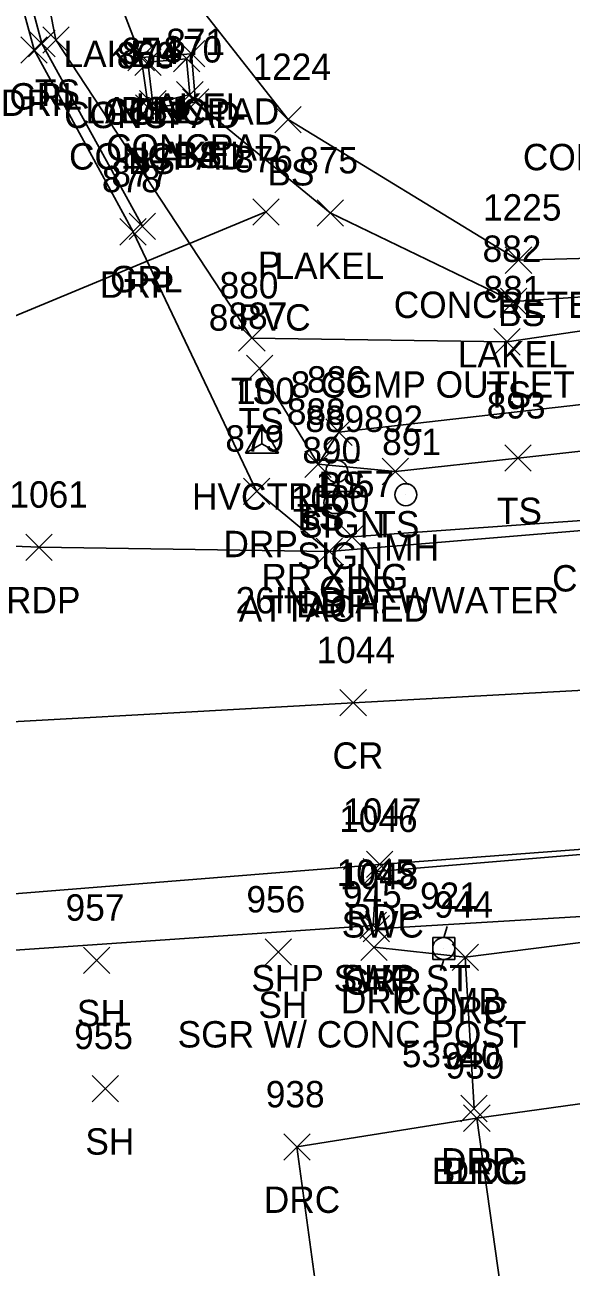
# Model space of a CAD drawing. Extents: x 1716490 to 1717645, y 888034 to 890004.
# Drawn here: x 1716813.5 to 1716855, y 888185.6 to 888279.7 of the extents above; entities that cross this region are included whole.
import ezdxf

# ---------------------------------------------------------------- set-up
doc = ezdxf.new("R2010")
doc.units = 0
for name, color, linetype in [('C_A', 7, 'Continuous'), ('C_I', 7, 'Continuous'), ('CPSM', 7, 'Continuous'), ('D_A', 7, 'Continuous'), ('D_C', 7, 'Continuous'), ('D_I', 7, 'Continuous'), ('D_TIC', 7, 'Continuous'), ('DCP', 7, 'Continuous'), ('L_A', 7, 'Continuous'), ('L_I', 7, 'Continuous'), ('L_TIC', 7, 'Continuous'), ('LAWE', 7, 'Continuous'), ('LBC', 7, 'Continuous'), ('LELB', 7, 'Continuous'), ('LS', 7, 'Continuous'), ('P_A', 7, 'Continuous'), ('P_I', 7, 'Continuous'), ('P_TIC', 7, 'Continuous'), ('PET', 7, 'Continuous'), ('PRC', 7, 'Continuous'), ('PSP', 7, 'Continuous'), ('R_A', 7, 'Continuous'), ('R_C', 7, 'Continuous'), ('R_I', 7, 'Continuous'), ('R_TIC', 7, 'Continuous'), ('RDP', 7, 'Continuous'), ('RGR', 7, 'Continuous'), ('RSW', 7, 'Continuous'), ('S_A', 7, 'Continuous'), ('S_C', 7, 'Continuous'), ('S_I', 7, 'Continuous'), ('SSGN', 7, 'Continuous'), ('U_A', 7, 'Continuous'), ('U_C', 7, 'Continuous'), ('U_I', 7, 'Continuous'), ('UP', 7, 'Continuous'), ('UUMH', 7, 'Continuous')]:
    doc.layers.add(name, color=color, linetype=linetype)

msp = doc.modelspace()

# ---------------------------------------------------------------- linework, layer by layer
at = {"layer": 'CPSM'}
for p, q in [((1716830.281, 888247.276), (1716831.531, 888249.441)), ((1716832.781, 888247.276), (1716831.531, 888249.441)), ((1716831.531, 888247.997), (1716831.531, 888249.441)), ((1716830.281, 888247.276), (1716831.531, 888247.997)), ((1716831.531, 888247.997), (1716831.531, 888247.997)), ((1716831.531, 888247.997), (1716832.781, 888247.276)), ((1716830.281, 888247.276), (1716832.781, 888247.276))]:
    msp.add_line(p, q, dxfattribs=at)
at = {"layer": 'D_TIC'}
for points in [[(1716830.837, 888264.562), (1716832.837, 888266.562)], [(1716832.837, 888264.562), (1716830.837, 888266.562)]]:
    msp.add_lwpolyline(points, dxfattribs=at)
at = {"layer": 'DCP'}
msp.add_lwpolyline([(1716831.837, 888265.562), (1716770.869, 888240.276)], dxfattribs=at)
at = {"layer": 'L_TIC'}
for points in [[(1716814.908, 888277.599), (1716816.908, 888279.599)], [(1716816.908, 888277.599), (1716814.908, 888279.599)], [(1716821.371, 888276.267), (1716823.371, 888278.267)], [(1716823.371, 888276.267), (1716821.371, 888278.267)], [(1716821.371, 888276.267), (1716823.371, 888278.267)], [(1716823.371, 888276.267), (1716821.371, 888278.267)], [(1716821.882, 888275.912), (1716823.882, 888277.912)], [(1716823.882, 888275.912), (1716821.882, 888277.912)], [(1716824.821, 888276.17), (1716826.821, 888278.17)], [(1716826.821, 888276.17), (1716824.821, 888278.17)], [(1716825.189, 888276.556), (1716827.189, 888278.556)], [(1716827.189, 888276.556), (1716825.189, 888278.556)], [(1716825.062, 888273.45), (1716827.062, 888275.45)], [(1716827.062, 888273.45), (1716825.062, 888275.45)], [(1716825.504, 888272.884), (1716827.504, 888274.884)], [(1716827.504, 888272.884), (1716825.504, 888274.884)], [(1716825.504, 888272.884), (1716827.504, 888274.884)], [(1716827.504, 888272.884), (1716825.504, 888274.884)], [(1716821.932, 888272.438), (1716823.932, 888274.438)], [(1716823.932, 888272.438), (1716821.932, 888274.438)], [(1716822.255, 888272.772), (1716824.255, 888274.772)], [(1716824.255, 888272.772), (1716822.255, 888274.772)], [(1716832.507, 888271.565), (1716834.507, 888273.565)], [(1716834.507, 888271.565), (1716832.507, 888273.565)], [(1716835.716, 888264.482), (1716837.716, 888266.482)], [(1716837.716, 888264.482), (1716835.716, 888266.482)], [(1716849.988, 888260.906), (1716851.988, 888262.906)], [(1716851.988, 888260.906), (1716849.988, 888262.906)], [(1716849.622, 888257.774), (1716851.622, 888259.774)], [(1716851.622, 888257.774), (1716849.622, 888259.774)], [(1716829.764, 888255.002), (1716831.764, 888257.002)], [(1716831.764, 888255.002), (1716829.764, 888257.002)], [(1716849.124, 888254.716), (1716851.124, 888256.716)], [(1716851.124, 888254.716), (1716849.124, 888256.716)], [(1716830.352, 888252.697), (1716832.352, 888254.697)], [(1716832.352, 888252.697), (1716830.352, 888254.697)], [(1716836.365, 888247.868), (1716838.365, 888249.868)], [(1716838.365, 888247.868), (1716836.365, 888249.868)], [(1716849.938, 888245.905), (1716851.938, 888247.905)], [(1716851.938, 888245.905), (1716849.938, 888247.905)], [(1716834.782, 888245.432), (1716836.782, 888247.432)], [(1716836.782, 888245.432), (1716834.782, 888247.432)], [(1716834.782, 888245.432), (1716836.782, 888247.432)], [(1716836.782, 888245.432), (1716834.782, 888247.432)], [(1716840.647, 888244.886), (1716842.647, 888246.886)], [(1716842.647, 888244.886), (1716840.647, 888246.886)], [(1716818.002, 888207.843), (1716820.002, 888209.843)], [(1716820.002, 888207.843), (1716818.002, 888209.843)], [(1716831.77, 888208.468), (1716833.77, 888210.468)], [(1716833.77, 888208.468), (1716831.77, 888210.468)], [(1716818.65, 888198.11), (1716820.65, 888200.11)], [(1716820.65, 888198.11), (1716818.65, 888200.11)], [(1716846.826, 888195.875), (1716848.826, 888197.875)], [(1716848.826, 888195.875), (1716846.826, 888197.875)]]:
    msp.add_lwpolyline(points, dxfattribs=at)
at = {"layer": 'LAWE'}
msp.add_lwpolyline([(1716792.923, 888333.593), (1716808.09, 888324.58), (1716820.08, 888290.735), (1716820.719, 888281.539), (1716822.371, 888277.267), (1716826.189, 888277.556), (1716826.504, 888273.884), (1716836.716, 888265.482), (1716850.622, 888258.774), (1716877.174, 888260.555), (1716881.322, 888255.897), (1716887.736, 888253.856), (1716892.995, 888253.305), (1716893.169, 888249.274), (1716879.794, 888244.823)], dxfattribs=at)
at = {"layer": 'LBC'}
msp.add_lwpolyline([(1716884.889, 888132.553), (1716884.371, 888132.666), (1716857.375, 888128.726), (1716852.404, 888164.292), (1716847.826, 888196.875), (1716876.377, 888200.838), (1716883.534, 888201.862), (1716883.701, 888201.987), (1716884.835, 888201.978)], dxfattribs=at)
at = {"layer": 'LELB'}
for points in [[(1716798.784, 888338.684), (1716807.198, 888328.202), (1716816.689, 888310.638), (1716822.622, 888293.629), (1716826.404, 888294.991), (1716827.92, 888291.14), (1716823.715, 888289.67), (1716822.512, 888293.041), (1716821.152, 888288.315), (1716833.507, 888272.565), (1716850.988, 888261.906), (1716864.723, 888262.295), (1716881.119, 888261.054)], [(1716791.288, 888331.615), (1716796.122, 888325.707), (1716805.751, 888321.457), (1716813.357, 888291.514), (1716815.908, 888278.599), (1716830.764, 888256.002), (1716850.124, 888255.716), (1716867.758, 888258.309)], [(1716822.371, 888277.267), (1716822.932, 888273.438), (1716826.504, 888273.884)], [(1716831.352, 888253.697), (1716835.782, 888246.432), (1716841.647, 888245.886), (1716850.938, 888246.905), (1716869.789, 888249.001), (1716870.22, 888257.561), (1716875.534, 888257.948), (1716880.311, 888254.139), (1716887.482, 888251.965), (1716891.986, 888252.334), (1716891.594, 888250.562), (1716886.869, 888248.35), (1716879.09, 888248.225)], [(1716867.758, 888258.309), (1716868.17, 888252.377), (1716837.365, 888248.868), (1716835.782, 888246.432)]]:
    msp.add_lwpolyline(points, dxfattribs=at)
at = {"layer": 'LS'}
for points in [[(1716826.062, 888274.45), (1716825.821, 888277.17), (1716822.882, 888276.912), (1716823.255, 888273.772)], [(1716823.255, 888273.772), (1716826.062, 888274.45)]]:
    msp.add_lwpolyline(points, dxfattribs=at)
at = {"layer": 'P_TIC'}
for points in [[(1716813.633, 888239.145), (1716815.633, 888241.145)], [(1716815.633, 888239.145), (1716813.633, 888241.145)], [(1716835.634, 888238.831), (1716837.634, 888240.831)], [(1716837.634, 888238.831), (1716835.634, 888240.831)], [(1716837.45, 888227.358), (1716839.45, 888229.358)], [(1716839.45, 888227.358), (1716837.45, 888229.358)], [(1716839.455, 888215.113), (1716841.455, 888217.113)], [(1716841.455, 888215.113), (1716839.455, 888217.113)], [(1716838.964, 888210.481), (1716840.964, 888212.481)], [(1716840.964, 888210.481), (1716838.964, 888212.481)]]:
    msp.add_lwpolyline(points, dxfattribs=at)
at = {"layer": 'PET'}
msp.add_lwpolyline([(1716669.133, 888208.315), (1716709.505, 888208.714), (1716740.373, 888211.068), (1716775.556, 888211.777), (1716802.021, 888213.013), (1716840.455, 888216.113), (1716878.657, 888218.974), (1716877.597, 888230.504), (1716876.883, 888242.851), (1716857.915, 888241.594), (1716836.634, 888239.831), (1716814.633, 888240.145), (1716785.061, 888241.323), (1716771.928, 888239.872), (1716746.815, 888241.658), (1716719.438, 888242.78), (1716699.752, 888242.907), (1716680.829, 888242.531), (1716671.322, 888244.592)], dxfattribs=at)
at = {"layer": 'PRC'}
msp.add_lwpolyline([(1716669.076, 888220.596), (1716706.499, 888221.389), (1716739.728, 888221.602), (1716772.982, 888225.054), (1716801.229, 888226.279), (1716838.45, 888228.358), (1716877.597, 888230.504)], dxfattribs=at)
at = {"layer": 'PSP'}
msp.add_lwpolyline([(1716669.372, 888204.532), (1716709.372, 888205.407), (1716740.477, 888206.521), (1716776.451, 888207.971), (1716801.777, 888208.857), (1716839.964, 888211.481)], dxfattribs=at)
at = {"layer": 'R_TIC'}
for points in [[(1716813.245, 888276.838), (1716815.245, 888278.838)], [(1716815.245, 888276.838), (1716813.245, 888278.838)], [(1716813.838, 888277.323), (1716815.838, 888279.323)], [(1716815.838, 888277.323), (1716813.838, 888279.323)], [(1716821.467, 888263.473), (1716823.467, 888265.473)], [(1716823.467, 888263.473), (1716821.467, 888265.473)], [(1716820.755, 888263.054), (1716822.755, 888265.054)], [(1716822.755, 888263.054), (1716820.755, 888265.054)], [(1716830.123, 888243.394), (1716832.123, 888245.394)], [(1716832.123, 888243.394), (1716830.123, 888245.394)], [(1716837.37, 888239.943), (1716839.37, 888241.943)], [(1716839.37, 888239.943), (1716837.37, 888241.943)], [(1716835.634, 888238.831), (1716837.634, 888240.831)], [(1716837.634, 888238.831), (1716835.634, 888240.831)], [(1716839.214, 888214.564), (1716841.214, 888216.564)], [(1716841.214, 888214.564), (1716839.214, 888216.564)], [(1716838.964, 888210.481), (1716840.964, 888212.481)], [(1716840.964, 888210.481), (1716838.964, 888212.481)], [(1716839.215, 888210.23), (1716841.215, 888212.23)], [(1716841.215, 888210.23), (1716839.215, 888212.23)], [(1716839.032, 888208.825), (1716841.032, 888210.825)], [(1716841.032, 888208.825), (1716839.032, 888210.825)], [(1716845.948, 888208.068), (1716847.948, 888210.068)], [(1716847.948, 888208.068), (1716845.948, 888210.068)], [(1716845.948, 888208.068), (1716847.948, 888210.068)], [(1716847.948, 888208.068), (1716845.948, 888210.068)], [(1716846.619, 888196.606), (1716848.619, 888198.606)], [(1716848.619, 888196.606), (1716846.619, 888198.606)], [(1716846.826, 888195.875), (1716848.826, 888197.875)], [(1716848.826, 888195.875), (1716846.826, 888197.875)], [(1716833.184, 888193.695), (1716835.184, 888195.695)], [(1716835.184, 888193.695), (1716833.184, 888195.695)]]:
    msp.add_lwpolyline(points, dxfattribs=at)
at = {"layer": 'RDP'}
for points in [[(1716788.401, 888319.776), (1716804.113, 888319.602), (1716810.581, 888291.273), (1716814.245, 888277.838), (1716821.755, 888264.054), (1716831.123, 888244.394), (1716836.634, 888239.831)], [(1716876.377, 888200.838), (1716875.716, 888209.526), (1716867.474, 888211.687), (1716846.948, 888209.068)], [(1716847.619, 888197.606), (1716846.948, 888209.068), (1716840.032, 888209.825)], [(1716857.375, 888128.726), (1716843.611, 888126.909), (1716838.26, 888164.679), (1716834.184, 888194.695), (1716847.826, 888196.875)]]:
    msp.add_lwpolyline(points, dxfattribs=at)
at = {"layer": 'RGR'}
for points in [[(1716789.776, 888320.755), (1716804.987, 888320.51), (1716811.337, 888291.322), (1716814.838, 888278.323), (1716822.467, 888264.473)], [(1716877.112, 888243.702), (1716838.37, 888240.943)], [(1716840.215, 888211.23), (1716878.419, 888213.528)]]:
    msp.add_lwpolyline(points, dxfattribs=at)
at = {"layer": 'RSW'}
msp.add_lwpolyline([(1716839.964, 888211.481), (1716840.214, 888215.564), (1716878.468, 888218.75), (1716878.816, 888213.646)], dxfattribs=at)
at = {"layer": 'SSGN'}
for p, q in [((1716835.56, 888246.736), (1716838.893, 888246.736)), ((1716837.206, 888245.903), (1716837.206, 888245.903)), ((1716835.414, 888244.361), (1716838.747, 888244.361)), ((1716837.061, 888243.527), (1716837.061, 888243.527))]:
    msp.add_line(p, q, dxfattribs=at)
for centre in [(1716837.206, 888245.903), (1716837.061, 888243.527)]:
    msp.add_circle(centre, 0.833, dxfattribs=at)
at = {"layer": 'UP'}
for p, q in [((1716845.569, 888211.403), (1716845.319, 888210.57)), ((1716844.485, 888208.903), (1716844.485, 888210.57)), ((1716844.485, 888210.57), (1716846.152, 888210.57)), ((1716846.152, 888210.57), (1716846.152, 888208.903)), ((1716846.152, 888208.903), (1716844.485, 888208.903)), ((1716845.069, 888208.07), (1716845.319, 888208.903)), ((1716845.319, 888209.737), (1716845.319, 888209.737))]:
    msp.add_line(p, q, dxfattribs=at)
msp.add_circle((1716845.319, 888209.737), 0.833, dxfattribs=at)
at = {"layer": 'UUMH'}
for p, q in [((1716842.442, 888244.13), (1716842.442, 888244.13)), ((1716843.275, 888244.13), (1716843.275, 888244.13))]:
    msp.add_line(p, q, dxfattribs=at)
msp.add_circle((1716842.442, 888244.13), 0.833, dxfattribs=at)

# ---------------------------------------------------------------- texts
at = {"layer": 'C_A'}
msp.add_text('HVCTRL', height=2, dxfattribs=at).set_placement((1716826.224, 888242.997))
at = {"layer": 'C_I'}
msp.add_text('100', height=2, dxfattribs=at).set_placement((1716829.571, 888250.997))
at = {"layer": 'D_A'}
msp.add_text('P', height=2, dxfattribs=at).set_placement((1716831.215, 888260.562))
at = {"layer": 'D_C'}
for s, p in [('8 PVC', (1716827.498, 888256.562)), ('8 CGMP OUTLET ORIGIN UNKNOWN', (1716833.708, 888251.48))]:
    msp.add_text(s, height=2, dxfattribs=at).set_placement(p)
at = {"layer": 'D_I'}
msp.add_text('876', height=2, dxfattribs=at).set_placement((1716829.42, 888268.562))
at = {"layer": 'L_A'}
for s, p in [('LAKEL', (1716816.483, 888276.539)), ('TS', (1716814.318, 888273.599)), ('CONCPAD', (1716816.528, 888271.912)), ('LAKEL', (1716818.135, 888272.267)), ('CONCPAD', (1716819.467, 888272.17)), ('BS', (1716820.812, 888272.267)), ('LAKEL', (1716821.953, 888272.556)), ('CONCPAD', (1716819.708, 888269.45)), ('CONCPAD', (1716816.901, 888268.772)), ('BS', (1716821.373, 888268.438)), ('LAKEL', (1716822.267, 888268.884)), ('BS', (1716824.944, 888268.884)), ('BS', (1716831.948, 888267.565)), ('LAKEL', (1716832.479, 888260.482)), ('BS', (1716849.429, 888256.906)), ('LAKEL', (1716846.386, 888253.774)), ('TS', (1716829.173, 888251.002)), ('TS', (1716848.533, 888250.716)), ('TS', (1716829.761, 888248.697)), ('BS', (1716835.805, 888243.868)), ('TS', (1716849.347, 888241.905)), ('TS', (1716834.192, 888241.432)), ('BS', (1716834.223, 888241.432)), ('TS', (1716840.056, 888240.886)), ('SH', (1716831.258, 888204.468)), ('SH', (1716817.49, 888203.843)), ('SH', (1716818.138, 888194.11)), ('BLDG', (1716844.417, 888191.875))]:
    msp.add_text(s, height=2, dxfattribs=at).set_placement(p)
at = {"layer": 'L_I'}
for s, p in [('874', (1716820.893, 888276.772)), ('870', (1716824.055, 888276.884)), ('870', (1716824.055, 888276.884)), ('871', (1716824.267, 888277.45)), ('869', (1716820.514, 888276.438)), ('1224', (1716830.814, 888275.565)), ('875', (1716834.353, 888268.482)), ('1225', (1716848.295, 888264.906)), ('882', (1716848.26, 888261.774)), ('880', (1716828.315, 888259.002)), ('881', (1716848.329, 888258.716)), ('887', (1716828.99, 888256.697)), ('886', (1716834.947, 888251.868)), ('888', (1716833.42, 888249.432)), ('888', (1716833.42, 888249.432)), ('893', (1716848.576, 888249.905)), ('892', (1716839.285, 888248.886)), ('957', (1716816.64, 888211.843)), ('956', (1716830.352, 888212.468)), ('955', (1716817.288, 888202.11)), ('939', (1716845.456, 888199.875))]:
    msp.add_text(s, height=2, dxfattribs=at).set_placement(p)
at = {"layer": 'P_A'}
for s, p in [('RDP', (1716812.121, 888235.145)), ('RDP', (1716834.122, 888234.831)), ('CR', (1716836.883, 888223.358)), ('RDP', (1716837.943, 888211.113)), ('SHP', (1716837.499, 888206.481))]:
    msp.add_text(s, height=2, dxfattribs=at).set_placement(p)
at = {"layer": 'P_I'}
for s, p in [('1061', (1716812.381, 888243.145)), ('1060', (1716833.728, 888242.831)), ('1044', (1716835.678, 888231.358)), ('1047', (1716837.683, 888219.113)), ('1045', (1716837.192, 888214.481))]:
    msp.add_text(s, height=2, dxfattribs=at).set_placement(p)
at = {"layer": 'R_A'}
for s, p in [('DRP', (1716811.733, 888272.838)), ('GRL', (1716812.382, 888273.323)), ('DRP', (1716819.243, 888259.054)), ('GRL', (1716820.011, 888259.473)), ('DRP', (1716828.611, 888239.394)), ('CURBC', (1716853.534, 888236.793)), ('GRR', (1716835.859, 888235.943)), ('DRP', (1716834.122, 888234.831)), ('SWC', (1716837.576, 888210.564)), ('SHP SWC ST', (1716830.727, 888206.481)), ('GRR', (1716837.703, 888206.23)), ('DRP', (1716837.52, 888204.825)), ('DRC', (1716844.436, 888204.068)), ('DRP', (1716844.436, 888204.068)), ('DRP', (1716845.107, 888192.606)), ('DRC', (1716845.314, 888191.875)), ('DRC', (1716831.672, 888189.695))]:
    msp.add_text(s, height=2, dxfattribs=at).set_placement(p)
at = {"layer": 'R_C'}
for s, p in [('CONCRETE 2.5 X 2', (1716851.32, 888268.72)), ('CONCRETE TIE TO LAST WITH RXR', (1716841.527, 888257.523)), ('SGR W/ CONC POST', (1716825.136, 888202.23))]:
    msp.add_text(s, height=2, dxfattribs=at).set_placement(p)
at = {"layer": 'R_I'}
for s, p in [('877', (1716820.105, 888267.473)), ('878', (1716819.393, 888267.054)), ('879', (1716828.753, 888247.394)), ('1057', (1716835.599, 888243.943)), ('1060', (1716833.728, 888242.831)), ('1046', (1716837.387, 888218.564)), ('1045', (1716837.192, 888214.481)), ('1048', (1716837.443, 888214.23)), ('945', (1716837.67, 888212.825)), ('944', (1716844.586, 888212.068)), ('944', (1716844.586, 888212.068)), ('940', (1716845.17, 888200.606)), ('939', (1716845.456, 888199.875)), ('938', (1716831.822, 888197.695))]:
    msp.add_text(s, height=2, dxfattribs=at).set_placement(p)
at = {"layer": 'S_A'}
for p in [(1716834.344, 888240.883), (1716834.198, 888238.507)]:
    msp.add_text('SIGN', height=2, dxfattribs=at).set_placement(p)
at = {"layer": 'S_C'}
for s, p in [('RR XING', (1716831.494, 888236.883)), ('ATTACHED', (1716829.773, 888234.507))]:
    msp.add_text(s, height=2, dxfattribs=at).set_placement(p)
at = {"layer": 'S_I'}
for s, p in [('889', (1716834.817, 888248.883)), ('890', (1716834.592, 888246.507))]:
    msp.add_text(s, height=2, dxfattribs=at).set_placement(p)
at = {"layer": 'U_A'}
for s, p in [('MH', (1716840.804, 888239.13)), ('COMB', (1716841.704, 888204.737))]:
    msp.add_text(s, height=2, dxfattribs=at).set_placement(p)
at = {"layer": 'U_C'}
for s, p in [('26IN DIA. WWATER', (1716829.537, 888235.13)), ('53-2', (1716842.137, 888200.737))]:
    msp.add_text(s, height=2, dxfattribs=at).set_placement(p)
at = {"layer": 'U_I'}
for s, p in [('891', (1716840.647, 888247.13)), ('921', (1716843.523, 888212.737))]:
    msp.add_text(s, height=2, dxfattribs=at).set_placement(p)

doc.saveas('drawing.dxf')
